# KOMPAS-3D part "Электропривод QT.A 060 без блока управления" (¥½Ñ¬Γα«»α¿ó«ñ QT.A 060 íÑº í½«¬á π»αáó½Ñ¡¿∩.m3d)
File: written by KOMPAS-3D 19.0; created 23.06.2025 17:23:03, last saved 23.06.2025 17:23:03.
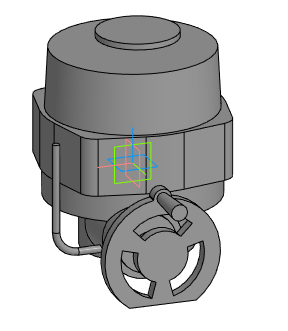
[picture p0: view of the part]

Document properties: Автор: Евгений; Полное имя файла: E:\Dendor Работа Сачек\3D для проектировщиков\3.5 Тип QT.А Электропривод\stp_Электропривод QT.A без блока управления\Электропривод QT.A 060 без блока управления.m3d

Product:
- Part/product: Электропривод QT.A 060 без блока управления

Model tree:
1. Операция без истории:1  (labels: Электропривод QT.A 060 без блока управления)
